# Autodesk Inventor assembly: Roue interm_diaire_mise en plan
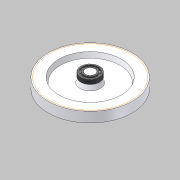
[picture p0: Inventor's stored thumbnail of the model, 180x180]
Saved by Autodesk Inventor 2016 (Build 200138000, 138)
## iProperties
Created: 2011-10
Part Number: Roue interm_diaire_mise en plan
Document SubType Name: Assembly
Designer: Bruno
Mass: 27.4005 g
Surface Area: 117.763 cm^2
Volume: 27.4005 cm^3
Density: 1 g/cm^3
Author: Bruno
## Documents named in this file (3)
- C:\Users\uhl\Desktop\Cric-Inventor\Roue interm_diaire_mise en plan.iam
- C:\Users\uhl\Desktop\Cric-Inventor\roue Z68-Z11_mise en plan.ipt
- C:\Users\uhl\Desktop\Cric-Inventor\Roulement_r1rb15_D_faut.iam
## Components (2 placed, 2 different names)
1. roue Z68-Z11_mise en plan:1
2. Roulement_r1rb15_D_faut:1 [sub-assembly]
